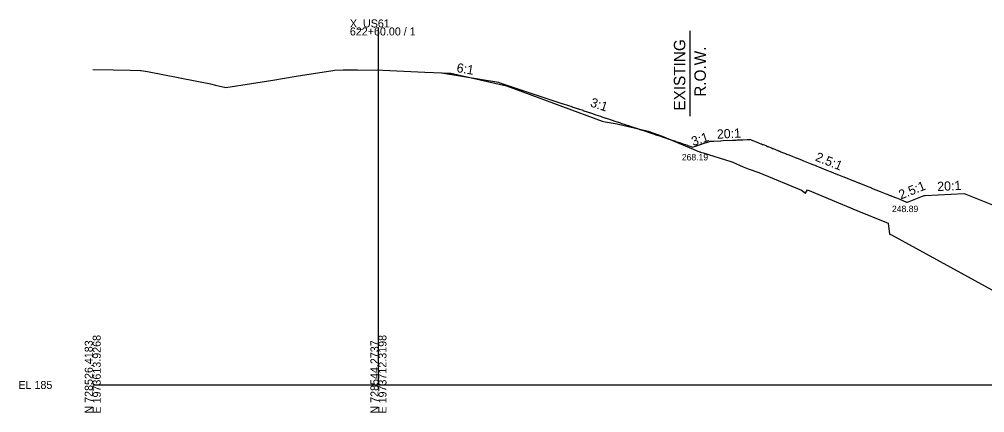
# Model space of a CAD drawing. Extents: x -26 to 1629, y -25 to 9635.
# Drawn here: x -25.7 to 312.2, y 6490.3 to 6627.8 of the extents above; entities that cross this region are included whole.
import ezdxf

# ---------------------------------------------------------------- set-up
doc = ezdxf.new("R2010")
doc.units = 0
for name, color, linetype in [('Default', 7, 'Continuous'), ('Draft_XS_Grid', 7, 'Continuous'), ('DTM CONTOURS_MAJOR', 7, 'Continuous'), ('DTM_X_GROUND', 7, 'Continuous'), ('XS_CELL', 7, 'Continuous'), ('XS_P_GROUND', 7, 'Continuous'), ('XS_P_TX_DCH', 7, 'Continuous'), ('XS_P_TX_FS_BS', 7, 'Continuous'), ('XS_X_ROW', 7, 'Continuous')]:
    doc.layers.add(name, color=color, linetype=linetype)

msp = doc.modelspace()

# ---------------------------------------------------------------- linework, layer by layer
at = {"layer": 'DTM_X_GROUND'}
msp.add_lwpolyline([(0, 6610.28), (7.11, 6610.16), (13.05, 6610.06), (16.7, 6609.91), (16.9, 6609.9), (19.15, 6609.63), (41.27, 6605.28), (42.93, 6604.79), (46.61, 6604.04), (55.57, 6605.46), (63.01, 6606.61), (71.22, 6607.94), (84, 6610), (84.57, 6610.03), (87.61, 6610.21), (92.71, 6610.14), (101.52, 6610.01), (116.26, 6609.42), (122.3, 6609.17), (124.76, 6609.06), (125.34, 6609.04), (131.49, 6607.62), (144.8, 6604.57), (150.56, 6602.44), (178.28, 6592.28), (179.34, 6591.98), (183.57, 6591.34), (194.42, 6588.75), (199.31, 6586.94), (212.37, 6581.56), (212.39, 6581.56), (212.61, 6581.48), (212.74, 6581.44), (213.63, 6581.15), (223.28, 6578.15), (224.05, 6577.91), (227.65, 6576.29), (229.38, 6575.6), (233.06, 6574.3), (248.03, 6568.12), (249.4, 6567.01), (250.14, 6568.2), (267.43, 6560.99), (277.76, 6556.75), (278.33, 6556.55), (278.8, 6552.68), (279.53, 6552.46), (320.87, 6529.91)], dxfattribs=at)
at = {"layer": 'XS_CELL'}
for p, q in [((100, 6500), (100, 6625)), ((0, 6500), (100, 6500)), ((100, 6500), (550, 6500))]:
    msp.add_line(p, q, dxfattribs=at)
at = {"layer": 'XS_P_GROUND'}
for points in [[(122, 6609.19), (142, 6605.85)], [(142, 6605.85), (142.53, 6605.67), (164.2, 6598.45), (164.21, 6598.45), (164.58, 6598.32), (164.62, 6598.31), (166.11, 6597.82), (166.14, 6597.8), (167.63, 6597.31), (167.65, 6597.3), (168.4, 6597.05), (168.44, 6597.04), (169.93, 6596.54), (169.97, 6596.53), (171.47, 6596.03), (171.49, 6596.02), (172.24, 6595.77), (172.28, 6595.76), (173.78, 6595.26), (173.8, 6595.25), (174.56, 6595), (174.59, 6594.99), (176.1, 6594.48), (176.12, 6594.48), (176.88, 6594.22), (176.9, 6594.22), (177.66, 6593.97), (177.67, 6593.96), (178.15, 6593.8), (178.17, 6593.8), (178.87, 6593.56), (178.88, 6593.56), (179.61, 6593.32), (179.71, 6593.28), (180, 6593.19), (180.54, 6593.01), (180.79, 6592.92), (182.19, 6592.45), (182.37, 6592.4), (183.88, 6591.89), (183.95, 6591.87), (184.72, 6591.61), (184.74, 6591.6), (184.78, 6591.59), (186.33, 6591.07), (186.58, 6590.99), (187.54, 6590.67), (188.73, 6590.28), (190.16, 6589.8), (190.32, 6589.74), (191.85, 6589.23), (191.93, 6589.21), (192.71, 6588.95), (192.73, 6588.94), (192.79, 6588.92), (193.09, 6588.82), (194.39, 6588.39), (195.14, 6588.14), (195.83, 6587.91), (195.95, 6587.87), (197.44, 6587.37), (197.57, 6587.33), (198.34, 6587.07), (198.38, 6587.06), (199.95, 6586.54), (200, 6586.52), (200.02, 6586.51), (200.81, 6586.25), (200.83, 6586.24), (201.62, 6585.98), (201.64, 6585.97), (202.44, 6585.71), (202.48, 6585.69), (202.77, 6585.6), (203.53, 6585.34), (203.59, 6585.32), (204, 6585.19), (204.07, 6585.16), (205.23, 6584.78), (205.41, 6584.71), (205.71, 6584.62), (206.48, 6584.36), (206.52, 6584.34), (208.09, 6583.82), (208.17, 6583.8), (208.28, 6583.76), (210, 6583.19), (210.63, 6583.4), (212.21, 6583.92), (212.29, 6583.95), (212.35, 6583.97), (212.66, 6584.07), (213.97, 6584.51), (214.77, 6584.77), (215.79, 6585.11), (216, 6585.19), (216.43, 6585.21), (217.21, 6585.25), (217.26, 6585.25), (219.66, 6585.37), (219.76, 6585.37), (219.78, 6585.37), (220.6, 6585.42), (220.68, 6585.42), (223.95, 6585.58), (223.96, 6585.58), (224.1, 6585.59), (224.11, 6585.59), (224.79, 6585.62), (224.8, 6585.63), (224.92, 6585.63), (224.96, 6585.63), (225.17, 6585.64), (225.67, 6585.67), (226.48, 6585.71), (227.2, 6585.75), (227.32, 6585.75), (227.41, 6585.76), (227.41, 6585.76), (227.46, 6585.76), (229.01, 6585.84), (229.18, 6585.84), (229.24, 6585.85), (229.91, 6585.88), (229.96, 6585.88), (230, 6585.89), (230.64, 6585.63), (230.71, 6585.6), (230.9, 6585.52), (231.02, 6585.48), (231.56, 6585.26), (231.57, 6585.26), (231.58, 6585.25), (232.42, 6584.92), (232.8, 6584.76), (233.26, 6584.58), (233.87, 6584.34), (234.09, 6584.25), (234.39, 6584.13), (234.59, 6584.05), (234.93, 6583.91), (235.54, 6583.67), (235.82, 6583.56), (236.16, 6583.42), (236.37, 6583.34), (236.62, 6583.24), (237.18, 6583.01), (237.53, 6582.87), (237.93, 6582.71), (238.15, 6582.63), (239.79, 6581.97), (239.93, 6581.91), (240.1, 6581.84), (240.48, 6581.69), (240.84, 6581.55), (241.45, 6581.31), (241.71, 6581.2), (242.47, 6580.9), (242.6, 6580.84), (242.69, 6580.81), (242.84, 6580.75), (243.29, 6580.57), (243.31, 6580.56), (244.21, 6580.2), (244.23, 6580.19), (246.46, 6579.3), (246.52, 6579.28), (248, 6578.68), (248.04, 6578.67), (248.78, 6578.37), (248.8, 6578.37), (251.02, 6577.48), (251.08, 6577.45), (253.28, 6576.57), (253.35, 6576.55), (254.07, 6576.26), (254.11, 6576.24), (256.58, 6575.25), (259.03, 6574.27), (259.2, 6574.2), (260.05, 6573.86), (260.08, 6573.85), (260.1, 6573.84), (260.96, 6573.5), (261, 6573.48), (262.72, 6572.8), (262.81, 6572.76), (266.25, 6571.38), (266.3, 6571.37), (268.03, 6570.67), (268.1, 6570.65), (270.7, 6569.61), (270.72, 6569.6), (271.59, 6569.25), (271.61, 6569.24), (272.49, 6568.89), (272.56, 6568.86), (275.54, 6567.67), (275.59, 6567.65), (277.87, 6566.74), (277.98, 6566.69), (279, 6566.29), (279.25, 6566.19), (279.42, 6566.12), (279.68, 6566.01), (281.3, 6565.37), (282.4, 6564.93), (284.81, 6563.96), (284.99, 6563.89), (285, 6563.89), (285.15, 6563.94), (291, 6566.29), (291.35, 6566.3), (305, 6566.99), (334.73, 6555.09)]]:
    msp.add_lwpolyline(points, dxfattribs=at)
at = {"layer": 'XS_X_ROW'}
msp.add_line((209, 6623.86), (209, 6593.96), dxfattribs=at)

# ---------------------------------------------------------------- texts
at = {"layer": 'Default'}
msp.add_text('X', height=0.12, dxfattribs=at).set_placement((141.96, 6605.79))
at = {"layer": 'Draft_XS_Grid'}
msp.add_text('-', height=0.0001, dxfattribs=at).set_placement((0, 6500))
at = {"layer": 'DTM CONTOURS_MAJOR'}
for p in [(121.96, 6609.13), (141.96, 6605.79), (203.96, 6585.13), (215.96, 6585.13), (229.96, 6585.83), (209.96, 6583.13), (278.96, 6566.23), (290.96, 6566.23), (304.96, 6566.93), (284.96, 6563.83)]:
    msp.add_text('X', height=0.12, dxfattribs=at).set_placement(p)
at = {"layer": 'XS_CELL'}
for s, p in [('X_US61', (90, 6625)), ('622+60.00 / 1', (90, 6622.2)), ('EL 185', (-26, 6498.6))]:
    msp.add_text(s, height=2.8, dxfattribs=at).set_placement(p)
for s, p in [('E 1973613.9268', (2.8, 6490)), ('E 1973712.3198', (102.8, 6490)), ('N 728526.4183', (0, 6490)), ('N 728544.2737', (100, 6490))]:
    msp.add_text(s, height=2.8, rotation=90, dxfattribs=at).set_placement(p)
at = {"layer": 'XS_P_TX_DCH'}
for s, p in [('268.19', (206.16, 6578.5)), ('248.89', (279.71, 6560.44))]:
    msp.add_text(s, height=2.25, dxfattribs=at).set_placement(p)
at = {"layer": 'XS_P_TX_FS_BS'}
for s, rotation, p in [('6:1', 350.5377, (127.17, 6609.41)), ('3:1', 341.5651, (173.89, 6597.46)), ('3:1', 18.4349, (210.13, 6583.47)), ('20:1', 2.8624, (218.51, 6586.08)), ('2.5:1', 338.1986, (252.61, 6578.51)), ('20:1', 2.8624, (295.62, 6567.78)), ('2.5:1', 21.8014, (282.82, 6564.83))]:
    msp.add_text(s, height=3.24, rotation=rotation, dxfattribs=at).set_placement(p)
at = {"layer": 'XS_X_ROW'}
for s, p in [('EXISTING', (207.37, 6595.93)), ('R.O.W.', (214.57, 6600.77))]:
    msp.add_text(s, height=4, rotation=90, dxfattribs=at).set_placement(p)

doc.saveas('drawing.dxf')
